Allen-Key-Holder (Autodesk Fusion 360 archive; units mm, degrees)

design "Allen-Key-Holder" references "Base"
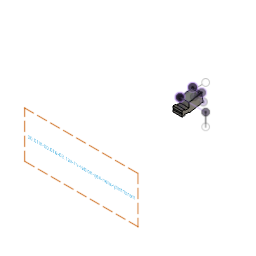
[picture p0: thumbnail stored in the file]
parameter "key_size" = 1.5
parameter "angle" = 10
parameter "head_length" = 10
parameter "padding" = 5
parameter "key_tolerance" = 1
parameter "calculated_width_height" = 14 (= "if(padding + padding + key_size < 14 mm; 14 mm; padding + padding + key_size)")
parameter "rounded_inset_depth" = 30
parameter "length_tolerance" = 5
component_insert "Component Insert" Text1-Height 5 AlongDistance 3.175 Linear Dimension-2 30 (= "rounded_inset_depth") Linear Dimension-3 30 (= "rounded_inset_depth") Side1Offset 0 TaperAngle 0 Linear Dimension-2 30 (= "rounded_inset_depth") Linear Dimension-3 30 (= "rounded_inset_depth") Side1Offset 0 TaperAngle 0 Radius 40
work_plane "WorkPlane5" AlongDistance 55.612
sketch "Sketch12" plane through (0, 55.6118, 0) normal (0, 1, 0) x axis (1, 0, 0)
  line L1 (40, -60) -> (0, -60)
  line L2 (40, -40) -> (40, -60)
  point P3 (40, -60)
  point P4 (40, -60)
  coincident P3 P4
  perpendicular L1 L2
sketch "Side" plane through (0, 0, 0) normal (1, 0, 0) x axis (0, 1, 0)
  line L1 (75.308, 63.473) -> (55.6118, 60)
  line L2 (95.6118, 60) -> (55.6118, 60)
  point P2 (55.6118, 60)
  point P3 (55.6118, 60)
  point P4 (75.308, 63.473)
  horizontal L2
  coincident P2 P3
  dimension "d66" distance P3 P4 = 20 (= "10 mm + head_length")
  dimension "d67" angle L1 L2 = 10 (= "angle")
work_plane "WorkPlane6" RotateAngle 90
sketch "Top" plane through (0, -8.5837, 48.6806) normal (0, 0.1736, -0.9848) x axis (0, 0.9848, 0.1736)
  line L1 (65.1859, 14) -> (65.1859, 0)
  line L2 (85.1859, 14) -> (65.1859, 14)
  line L3 (85.1859, 0) -> (65.1859, 0)
  line L4 (85.1859, 0) -> (85.1859, 14)
  point P3 (65.1859, 0)
  point P4 (65.1859, 0)
  point P2 (85.1859, 0)
  point P9 (85.1859, 0)
  point P5 (65.1859, 14)
  coincident P3 P4
  vertical L1
  perpendicular L1 L2
  equal L2 L3
  coincident P2 P9
  dimension "d69" distance P4 P5 = 14 (= "calculated_width_height")
extrude "Extrude18" new body sketch "Top" along a picked direction blind 14 (= "calculated_width_height")
extrude "Extrude15" new body of existing geometry blind 68
sketch "Front" plane through (0, 83.8917, 14.7924) normal (0, 0.9848, 0.1736) x axis (-1, 0, 0)
  line L1 (-14, 49.4316) -> (0, 49.4316)
  line L2 (-14, 35.4316) -> (-14, 49.4316)
  line L3 (0, 35.4316) -> (-14, 35.4316)
  line L4 (0, 49.4316) -> (0, 35.4316)
  line L5 (0, 35.4316) -> (-14, 49.4316)
  line L6 (-8.4434, 42.4316) -> (-7.7217, 43.6816)
  line L7 (-7.7217, 41.1816) -> (-8.4434, 42.4316)
  line L8 (-6.2783, 41.1816) -> (-7.7217, 41.1816)
  line L9 (-5.5566, 42.4316) -> (-6.2783, 41.1816)
  line L10 (-6.2783, 43.6816) -> (-5.5566, 42.4316)
  line L11 (-7.7217, 43.6816) -> (-6.2783, 43.6816)
  line L12 (0, 49.4316) -> (-14, 49.4316)
  point P3 (-14, 49.4316)
  point P6 (-14, 49.4316)
  point P5 (0, 35.4316)
  point P7 (0, 35.4316)
  point P14 (-7, 42.4316)
  coincident P3 P6
  coincident P5 P7
  midpoint L5 P14
  parallel L11 L12
  dimension "d91" distance P14 L11 = 1.25 (= "( key_size + key_tolerance ) / 2")
extrude "Extrude19" cut sketch "Front" profile of L6 L7 L8 L9 L10 L11 along a picked direction blind -10 (= "head_length * -1")
sketch "Sketch20" plane through (0, 0, 0) normal (-1, 0, 0) x axis (0, -1, 0)
  line L1 (-75.308, 63.473) -> (-55.6118, 60)
  line L2 (-77.7391, 49.6857) -> (-75.308, 63.473)
  line L3 (-58.0429, 46.2127) -> (-77.7391, 49.6857)
  line L4 (-55.6118, 60) -> (-58.0429, 46.2127)
  line L5 (-55.6118, 46.1062) -> (-55.6118, 60)
  line L6 (-58.0429, 46.2127) -> (-55.6118, 46.1062)
  point P6 (-55.6118, 60)
  point P8 (-55.6118, 60)
  point P7 (-58.0429, 46.2127)
  point P10 (-58.0429, 46.2127)
  coincident P6 P8
  vertical L5
  coincident P7 P10
extrude "Extrude20" add sketch "Sketch20" profile of L4 L5 L6 to an object
extrude "Extrude21" add of existing geometry to an object
extrude "Extrude22" cut of existing geometry to an object
fillet "Fillet3" radius 2
sketch "Sketch21" plane through (0, -6.1526, 34.8933) normal (0, 0.1736, -0.9848) x axis (-1, 0, 0)
  dimension "d102" = 2.5
sketch "File name" plane through (0, 0, 0) normal (0, 1, 0) x axis (1, 0, 0)
  dimension "d87" = 5
extrude "Extrude23" cut sketch "Sketch21" against normal blind 2

design "Base"
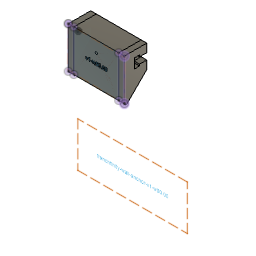
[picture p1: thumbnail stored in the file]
parameter "wall_anchor_height" = 60
parameter "wall_anchor_width" = 20
parameter "wall_anchor_angle" = 45
parameter "width_per_slot" = 40
parameter "slot_inner_width" = 8.5
parameter "slot_inner_height" = 4.5
parameter "slot_outer_width" = 5.6
parameter "slot_outer_height" = 6.5
parameter "slot_dept" = 15
parameter "print_tolerance" = 0.12
parameter "base_plate_thickness" = 16
parameter "base_plate_slot_height" = 50
parameter "wall_anchor_angle_rounded_border" = 1.5
parameter "base_plate_screw_hole_diameter" = 4
parameter "base_plate_screw_head_diameter" = 8
parameter "base_plate_screw_head_height" = 4
parameter "base_plate_screw_hole_side_distance" = 7
parameter "slot_screw_head_width" = 4.42 (= "4.3 mm + print_tolerance")
parameter "slot_screw_thread_width" = 2.12 (= "2 mm + print_tolerance")
parameter "slot_screw_head_height" = 2.12 (= "2 mm + print_tolerance")
parameter "width" = 50
parameter "filament_hole_width" = 1.7
sketch "Side" plane through (0, 0, 0) normal (1, 0, 0) x axis (0, 1, 0)
  line L1 (39.6118, 0) -> (19.6118, 0)
  line L2 (39.6118, 60) -> (39.6118, 0)
  line L3 (19.6118, 60) -> (39.6118, 60)
  line L4 (19.6118, 0) -> (19.6118, 60)
  line L5 (39.6118, 39.6118) -> (0, 0)
  line L6 (56.0196, 0) -> (0, 0)
  point P1 (0, 0)
  point P6 (0, 0)
  point P7 (39.6118, 39.6118)
  point P2 (19.6118, 0)
  point P3 (39.6118, 0)
  point P5 (19.6118, 60)
  horizontal L1
  vertical L2
  horizontal L3
  vertical L4
  horizontal L6
  coincident P1 P6
  coincident L2 P7
  dimension "d4" distance P2 P3 = 20 (= "wall_anchor_width")
  dimension "d5" distance P2 P5 = 60 (= "wall_anchor_height")
  dimension "d6" angle L5 L6 = 45 (= "wall_anchor_angle")
extrude "Extrude1" new body sketch "Side" profile of L1 L2 L3 L4 L5 along normal blind 40 (= "width_per_slot")
sketch "Slot LeftToRight" plane through (0, 0, 0) normal (-1, 0, 0) x axis (0, -1, 0)
  line L1 (-19.6118, 60) -> (-19.6118, 19.6118)
  line L2 (-39.6118, 60) -> (-19.6118, 60)
  line L3 (-39.6118, 39.6118) -> (-39.6118, 60)
  line L4 (-19.6118, 19.6118) -> (-39.6118, 39.6118)
  line L5 (-39.6118, 52.6059) -> (-39.6118, 49.8059)
  line L6 (-39.6118, 47.0059) -> (-39.6118, 49.8059)
  line L7 (-33.1118, 52.6059) -> (-39.6118, 52.6059)
  line L8 (-28.6118, 49.8059) -> (-39.6118, 49.8059)
  line L9 (-28.6118, 54.0559) -> (-28.6118, 49.8059)
  line L10 (-33.1118, 54.0559) -> (-28.6118, 54.0559)
  line L11 (-33.1118, 52.6059) -> (-33.1118, 54.0559)
  line L12 (-28.6118, 45.5559) -> (-28.6118, 49.8059)
  line L13 (-33.1118, 45.5559) -> (-28.6118, 45.5559)
  line L14 (-33.1118, 47.0059) -> (-33.1118, 45.5559)
  line L15 (-33.1118, 47.0059) -> (-39.6118, 47.0059)
  point P6 (-39.6118, 49.8059)
  point P7 (-39.6118, 52.6059)
  point P17 (-39.6118, 47.0059)
  point P9 (-33.1118, 52.6059)
  point P16 (-33.1118, 47.0059)
  point P10 (-28.6118, 49.8059)
  point P13 (-28.6118, 49.8059)
  point P11 (-28.6118, 54.0559)
  point P14 (-28.6118, 45.5559)
  point P12 (-33.1118, 54.0559)
  point P15 (-33.1118, 45.5559)
  midpoint L3 P6
  parallel L3 L5
  parallel L3 L6
  perpendicular L3 L7
  perpendicular L6 L8
  perpendicular L8 L9
  perpendicular L9 L10
  symmetric P7 L8 P17
  symmetric P9 L8 P16
  symmetric P10 L8 P13
  symmetric L8 P11 P14
  symmetric L8 P12 P15
  dimension "d80" distance P6 P7 = 2.8 (= "slot_outer_width / 2")
  dimension "d82" distance P7 P9 = 6.5 (= "slot_outer_height")
  dimension "d84" distance P6 P10 = 11 (= "slot_outer_height + slot_inner_height")
  dimension "d85" distance P10 P11 = 4.25 (= "slot_inner_width / 2")
  dimension "d86" distance P11 P12 = 4.5 (= "slot_inner_height")
extrude "Extrude3" cut sketch "Slot LeftToRight" profile of L3 L5 L6 L7 L9 L10 L11 L12 L13 L14 L15 against normal blind 40 (magnitude of "width_per_slot * -1")
sketch "Plate" plane through (0, 39.6118, 0) normal (0, 1, 0) x axis (-1, 0, 0)
  line L1 (0, 39.6118) -> (-40, 39.6118)
  line L2 (-40, 60) -> (0, 60)
  line L3 (0, 10) -> (0, 60)
  line L4 (-40, 10) -> (-40, 60)
  line L5 (-40, 10) -> (0, 10)
  line L6 (-40, 47.0059) -> (0, 47.0059)
  line L7 (-40, 52.6059) -> (-40, 60)
  line L8 (0, 60) -> (0, 52.6059)
  line L9 (0, 52.6059) -> (-40, 52.6059)
  line L10 (-40, 60) -> (0, 60)
  line L11 (-40, 39.6118) -> (-40, 47.0059)
  line L12 (0, 47.0059) -> (0, 39.6118)
  point P2 (0, 60)
  point P3 (-40, 60)
  point P4 (0, 10)
  point P5 (-40, 10)
  perpendicular L1 L3
  perpendicular L1 L4
  dimension "d36" distance P2 P3 = 40 (= "width_per_slot")
  dimension "d37" distance P2 P4 = 50 (= "base_plate_slot_height")
  dimension "d39" distance P3 P5 = 50 (= "base_plate_slot_height")
extrude "Extrude6" new body sketch "Plate" profile of L1 L2 L3 L4 L5 L6 L7 L8 L9 L10 along normal blind 16 (= "base_plate_thickness") bodies "Base plate with slot"
sketch "Slot" plane through (0, 0, 0) normal (-1, 0, 0) x axis (0, -1, 0)
  line L1 (-19.6118, 60) -> (-19.6118, 19.6118)
  line L2 (-39.6118, 60) -> (-19.6118, 60)
  line L3 (-39.6118, 52.6059) -> (-39.6118, 60)
  line L4 (-33.1118, 52.6059) -> (-39.6118, 52.6059)
  line L5 (-33.1118, 54.0559) -> (-33.1118, 52.6059)
  line L6 (-28.6118, 54.0559) -> (-33.1118, 54.0559)
  line L7 (-28.6118, 45.5559) -> (-28.6118, 54.0559)
  line L8 (-33.1118, 45.5559) -> (-28.6118, 45.5559)
  line L9 (-33.1118, 47.0059) -> (-33.1118, 45.5559)
  line L10 (-39.6118, 47.0059) -> (-33.1118, 47.0059)
  line L11 (-39.6118, 39.6118) -> (-39.6118, 47.0059)
  line L12 (-19.6118, 19.6118) -> (-39.6118, 39.6118)
  line L13 (-33.1118, 52.6059) -> (-39.6118, 52.6059)
  line L14 (-33.1118, 54.0559) -> (-33.1118, 52.6059)
  line L15 (-28.6118, 54.0559) -> (-33.1118, 54.0559)
  line L16 (-28.6118, 45.5559) -> (-28.6118, 54.0559)
  line L17 (-33.1118, 45.5559) -> (-28.6118, 45.5559)
  line L18 (-33.1118, 47.0059) -> (-33.1118, 45.5559)
  line L19 (-39.6118, 47.0059) -> (-33.1118, 47.0059)
  line L20 (-39.6118, 10) -> (-39.6118, 60)
  line L21 (-32.9918, 52.4859) -> (-39.6118, 52.4859)
  line L22 (-32.9918, 53.9359) -> (-32.9918, 52.4859)
  line L23 (-28.7318, 53.9359) -> (-32.9918, 53.9359)
  line L24 (-28.7318, 45.6759) -> (-28.7318, 53.9359)
  line L25 (-32.9918, 45.6759) -> (-28.7318, 45.6759)
  line L26 (-32.9918, 47.1259) -> (-32.9918, 45.6759)
  line L27 (-39.6118, 47.1259) -> (-32.9918, 47.1259)
  line L28 (-33.1118, 52.6059) -> (-39.6118, 52.6059)
  line L29 (-33.1118, 52.6059) -> (-33.1118, 54.0559)
  line L30 (-28.6118, 54.0559) -> (-33.1118, 54.0559)
  line L31 (-28.6118, 45.5559) -> (-28.6118, 54.0559)
  line L32 (-33.1118, 45.5559) -> (-28.6118, 45.5559)
  line L33 (-33.1118, 47.0059) -> (-33.1118, 45.5559)
  line L34 (-39.6118, 47.0059) -> (-33.1118, 47.0059)
  line L35 (-39.6118, 47.0059) -> (-39.6118, 52.6059)
  line L36 (-49.1118, 52.6059) -> (-55.6118, 52.6059)
  line L37 (-49.1118, 52.6059) -> (-49.1118, 54.0559)
  line L38 (-44.6118, 54.0559) -> (-49.1118, 54.0559)
  line L39 (-44.6118, 45.5559) -> (-44.6118, 54.0559)
  line L40 (-49.1118, 45.5559) -> (-44.6118, 45.5559)
  line L41 (-49.1118, 47.0059) -> (-49.1118, 45.5559)
  line L42 (-55.6118, 47.0059) -> (-49.1118, 47.0059)
  line L43 (-55.6118, 47.0059) -> (-55.6118, 52.6059)
  point P15 (-39.6118, 52.6059)
  point P33 (-39.6118, 52.6059)
  point P16 (-33.1118, 52.6059)
  point P34 (-33.1118, 52.6059)
  point P17 (-33.1118, 54.0559)
  point P35 (-33.1118, 54.0559)
  point P36 (-33.1118, 52.6059)
  point P18 (-28.6118, 54.0559)
  point P37 (-28.6118, 54.0559)
  point P19 (-28.6118, 45.5559)
  point P38 (-28.6118, 45.5559)
  point P10 (-28.6118, 45.5559)
  point P39 (-28.6118, 45.5559)
  point P11 (-33.1118, 45.5559)
  point P40 (-33.1118, 45.5559)
  point P41 (-33.1118, 45.5559)
  point P12 (-33.1118, 47.0059)
  point P42 (-33.1118, 47.0059)
  point P21 (-33.1118, 47.0059)
  point P43 (-33.1118, 47.0059)
  point P22 (-39.6118, 47.0059)
  point P44 (-39.6118, 47.0059)
  point P45 (-39.6118, 52.6059)
  point P46 (-39.6118, 47.0059)
  coincident P15 P33
  coincident P16 P34
  coincident P17 P35
  coincident P16 P36
  coincident P18 P37
  coincident P19 P38
  coincident P10 P39
  coincident P11 P40
  coincident P11 P41
  coincident P12 P42
  coincident P21 P43
  coincident P22 P44
  coincident P15 P45
  coincident P22 P46
  dimension "d91" = 0.12 (= "print_tolerance")
  dimension "d96" R-Pattern1-uDistance = -16 (= "base_plate_thickness * -1")
  dimension "d97" R-Pattern1-vDistance = 0
extrude "Extrude7" add sketch "Slot" profile of L20 L24 L23 L27 L22 L25 L26 L21 against normal blind 40 (magnitude of "width_per_slot * -1")
extrude "Extrude8" cut sketch "Slot" profile of L36 L37 L38 L39 L40 L41 L42 L43 no distance stored
sketch "Sketch3" plane through (0, 0, 0) normal (-1, 0, 0) x axis (0, -1, 0)
  line L1 (-32.9918, 47.1259) -> (-39.6118, 47.1259)
  line L2 (-32.9918, 45.6759) -> (-32.9918, 47.1259)
  line L3 (-28.7318, 45.6759) -> (-32.9918, 45.6759)
  line L4 (-28.7318, 53.9359) -> (-28.7318, 45.6759)
  line L5 (-32.9918, 53.9359) -> (-28.7318, 53.9359)
  line L6 (-32.9918, 52.4859) -> (-32.9918, 53.9359)
  line L7 (-39.6118, 52.4859) -> (-32.9918, 52.4859)
  line L8 (-44.6118, 45.5559) -> (-44.6118, 54.0559)
  line L9 (-32.9918, 52.4859) -> (-39.6118, 52.4859)
  line L10 (-32.9918, 53.9359) -> (-32.9918, 52.4859)
  line L11 (-28.7318, 53.9359) -> (-32.9918, 53.9359)
  line L12 (-28.7318, 45.6759) -> (-28.7318, 53.9359)
  line L13 (-32.9918, 45.6759) -> (-28.7318, 45.6759)
  line L14 (-32.9918, 47.1259) -> (-32.9918, 45.6759)
  line L15 (-39.6118, 47.1259) -> (-32.9918, 47.1259)
  line L16 (-39.6118, 47.1259) -> (-39.6118, 52.4859)
  line L17 (-55.6118, 52.4859) -> (-48.9918, 52.4859)
  line L18 (-48.9918, 52.4859) -> (-48.9918, 53.9359)
  line L19 (-48.9918, 53.9359) -> (-44.7318, 53.9359)
  line L20 (-44.7318, 45.6759) -> (-44.7318, 53.9359)
  line L21 (-48.9918, 45.6759) -> (-44.7318, 45.6759)
  line L22 (-48.9918, 47.1259) -> (-48.9918, 45.6759)
  line L23 (-55.6118, 47.1259) -> (-48.9918, 47.1259)
  line L24 (-55.6118, 47.1259) -> (-55.6118, 52.4859)
  line L25 (-55.6118, 47.0059) -> (-49.1118, 47.0059)
  line L26 (-55.6118, 10) -> (-55.6118, 47.0059)
  line L27 (-39.6118, 10) -> (-55.6118, 10)
  line L28 (-39.6118, 47.1259) -> (-39.6118, 10)
  line L29 (-39.6118, 60) -> (-39.6118, 52.4859)
  line L30 (-55.6118, 60) -> (-39.6118, 60)
  line L31 (-55.6118, 52.6059) -> (-55.6118, 60)
  line L32 (-49.1118, 52.6059) -> (-55.6118, 52.6059)
  line L33 (-49.1118, 54.0559) -> (-49.1118, 52.6059)
  line L34 (-44.6118, 54.0559) -> (-49.1118, 54.0559)
  line L35 (-49.1118, 45.5559) -> (-44.6118, 45.5559)
  line L36 (-49.1118, 47.0059) -> (-49.1118, 45.5559)
  point P9 (-39.6118, 52.4859)
  point P20 (-39.6118, 52.4859)
  point P19 (-39.6118, 47.1259)
  point P21 (-39.6118, 47.1259)
  coincident P9 P20
  coincident P19 P21
  dimension "d105" R-Pattern1-vDistance = 0
extrude "Extrude3" new body sketch "Sketch3" profile of L17 L18 L19 L20 L21 L22 L23 L24 against normal blind 40 (magnitude of "width_per_slot * -1")
sketch "Screw hole" plane through (0, 28.6118, 0) normal (0, 1, 0) x axis (-1, 0, 0)
  line L1 (0, 54.0559) -> (0, 45.5559)
  line L2 (-40, 54.0559) -> (0, 54.0559)
  line L3 (-40, 45.5559) -> (-40, 54.0559)
  line L4 (0, 45.5559) -> (-40, 45.5559)
  line L5 (0, 45.5559) -> (-40, 54.0559)
  line L6 (-40, 45.5559) -> (0, 54.0559)
  circle C1 centre (-20, 49.8059) radius 2.21
  circle C2 centre (-20, 49.8059) radius 1.06
  point P4 (-40, 54.0559)
  point P6 (-40, 54.0559)
  point P2 (0, 45.5559)
  point P7 (0, 45.5559)
  point P3 (0, 54.0559)
  point P8 (0, 54.0559)
  point P5 (-40, 45.5559)
  point P9 (-40, 45.5559)
  point P10 (-20, 49.8059)
  coincident P4 P6
  coincident P2 P7
  coincident P3 P8
  coincident P5 P9
  midpoint L5 P10
  concentric C1 C2
  dimension "d119" diameter C1 = 4.42 (= "slot_screw_head_width")
  dimension "d120" diameter C2 = 2.12 (= "slot_screw_thread_width")
extrude "Extrude4" cut sketch "Screw hole" profile of C2 against normal blind 2000
extrude "Extrude5" cut sketch "Screw hole" profile of C1 C2 no distance stored
fillet "Fillet1" radius 1.5 (= "wall_anchor_angle_rounded_border")
work_plane "WorkPlane1" sketch "Slot LeftToRight" AlongDistance -20 (= "-width_per_slot / 2")
sketch "Screw head" plane through (20, 0, 0) normal (-1, 0, 0) x axis (0, -1, 0)
  line L1 (-28.6118, 52.0159) -> (-28.6118, 47.5959)
  line L2 (-26.4918, 52.0159) -> (-26.4918, 47.5959)
  line L3 (-26.4918, 48.7459) -> (-26.4918, 50.8659)
  line L4 (-26.4918, 50.8659) -> (-28.6118, 52.0159)
  line L5 (-26.4918, 52.0159) -> (-28.6118, 52.0159)
  point P3 (-28.6118, 52.0159)
  point P8 (-28.6118, 52.0159)
  point P6 (-26.4918, 50.8659)
  point P9 (-26.4918, 50.8659)
  point P10 (-28.6118, 52.0159)
  point P5 (-26.4918, 52.0159)
  point P11 (-26.4918, 52.0159)
  coincident P3 P8
  coincident P6 P9
  coincident P3 P10
  coincident P5 P11
revolve "Revolve1" sketch "Screw head" AlongAngle 360
sketch "Plate" plane through (0, 39.6118, 0) normal (0, 1, 0) x axis (-1, 0, 0)
  line L1 (0, 39.6118) -> (-40, 39.6118)
  line L2 (-40, 60) -> (0, 60)
  line L3 (0, 10) -> (0, 60)
  line L4 (-40, 10) -> (-40, 60)
  line L5 (-40, 10) -> (0, 10)
  line L6 (-40, 47.0059) -> (0, 47.0059)
  line L7 (-40, 39.6118) -> (-40, 47.0059)
  line L8 (0, 47.0059) -> (0, 39.6118)
  line L9 (0, 52.6059) -> (-40, 52.6059)
  line L10 (-40, 60) -> (0, 60)
  line L11 (0, 60) -> (0, 52.6059)
  line L12 (-40, 52.6059) -> (-40, 60)
  point P2 (0, 60)
  point P3 (-40, 60)
  point P4 (0, 10)
  point P5 (-40, 10)
  perpendicular L1 L3
  perpendicular L1 L4
  dimension "d36_1" distance P2 P3 = 40 (= "width_per_slot")
  dimension "d37_1" distance P2 P4 = 50 (= "base_plate_slot_height")
  dimension "d39_1" distance P3 P5 = 50 (= "base_plate_slot_height")
extrude "Extrude6" new body sketch "Plate" profile of L1 L2 L3 L4 L5 L6 L7 L8 L9 L10 along normal blind 16 (= "base_plate_thickness") named "d89_1" bodies "Base plate with slot"
sketch "Slot" plane through (0, 0, 0) normal (-1, 0, 0) x axis (0, -1, 0)
  line L1 (-19.6118, 60) -> (-19.6118, 23.2332)
  line L2 (-39.6118, 60) -> (-19.6118, 60)
  line L3 (-39.6118, 52.6059) -> (-39.6118, 60)
  line L4 (-33.1118, 52.6059) -> (-39.6118, 52.6059)
  line L5 (-33.1118, 54.0559) -> (-33.1118, 52.6059)
  line L6 (-28.6118, 54.0559) -> (-33.1118, 54.0559)
  line L7 (-28.6118, 45.5559) -> (-28.6118, 54.0559)
  line L8 (-33.1118, 45.5559) -> (-28.6118, 45.5559)
  line L9 (-33.1118, 47.0059) -> (-33.1118, 45.5559)
  line L10 (-39.6118, 47.0059) -> (-33.1118, 47.0059)
  line L11 (-39.6118, 39.6118) -> (-39.6118, 47.0059)
  line L12 (-22.1725, 22.1725) -> (-39.6118, 39.6118)
  line L13 (-33.1118, 52.6059) -> (-39.6118, 52.6059)
  line L14 (-33.1118, 54.0559) -> (-33.1118, 52.6059)
  line L15 (-28.6118, 54.0559) -> (-33.1118, 54.0559)
  line L16 (-28.6118, 45.5559) -> (-28.6118, 54.0559)
  line L17 (-33.1118, 45.5559) -> (-28.6118, 45.5559)
  line L18 (-33.1118, 47.0059) -> (-33.1118, 45.5559)
  line L19 (-39.6118, 47.0059) -> (-33.1118, 47.0059)
  line L20 (-39.6118, 10) -> (-39.6118, 60)
  line L21 (-32.9918, 52.4859) -> (-39.6118, 52.4859)
  line L22 (-32.9918, 53.9359) -> (-32.9918, 52.4859)
  line L23 (-28.7318, 53.9359) -> (-32.9918, 53.9359)
  line L24 (-28.7318, 45.6759) -> (-28.7318, 53.9359)
  line L25 (-32.9918, 45.6759) -> (-28.7318, 45.6759)
  line L26 (-32.9918, 47.1259) -> (-32.9918, 45.6759)
  line L27 (-39.6118, 47.1259) -> (-32.9918, 47.1259)
  line L28 (-33.1118, 52.6059) -> (-39.6118, 52.6059)
  line L29 (-33.1118, 52.6059) -> (-33.1118, 54.0559)
  line L30 (-28.6118, 54.0559) -> (-33.1118, 54.0559)
  line L31 (-28.6118, 45.5559) -> (-28.6118, 54.0559)
  line L32 (-33.1118, 45.5559) -> (-28.6118, 45.5559)
  line L33 (-33.1118, 47.0059) -> (-33.1118, 45.5559)
  line L34 (-39.6118, 47.0059) -> (-33.1118, 47.0059)
  line L35 (-39.6118, 47.0059) -> (-39.6118, 52.6059)
  line L36 (-49.1118, 52.6059) -> (-55.6118, 52.6059)
  line L37 (-49.1118, 52.6059) -> (-49.1118, 54.0559)
  line L38 (-44.6118, 54.0559) -> (-49.1118, 54.0559)
  line L39 (-44.6118, 45.5559) -> (-44.6118, 54.0559)
  line L40 (-49.1118, 45.5559) -> (-44.6118, 45.5559)
  line L41 (-49.1118, 47.0059) -> (-49.1118, 45.5559)
  line L42 (-55.6118, 47.0059) -> (-49.1118, 47.0059)
  line L43 (-55.6118, 47.0059) -> (-55.6118, 52.6059)
  arc A1 centre (-21.1118, 23.2332) radius 1.5 clockwise from (-19.6118, 23.2332) to (-22.1725, 22.1725)
  point P15 (-39.6118, 52.6059)
  point P33 (-39.6118, 52.6059)
  point P16 (-33.1118, 52.6059)
  point P34 (-33.1118, 52.6059)
  point P17 (-33.1118, 54.0559)
  point P35 (-33.1118, 54.0559)
  point P36 (-33.1118, 52.6059)
  point P18 (-28.6118, 54.0559)
  point P37 (-28.6118, 54.0559)
  point P19 (-28.6118, 45.5559)
  point P38 (-28.6118, 45.5559)
  point P10 (-28.6118, 45.5559)
  point P39 (-28.6118, 45.5559)
  point P11 (-33.1118, 45.5559)
  point P40 (-33.1118, 45.5559)
  point P41 (-33.1118, 45.5559)
  point P12 (-33.1118, 47.0059)
  point P42 (-33.1118, 47.0059)
  point P21 (-33.1118, 47.0059)
  point P43 (-33.1118, 47.0059)
  point P22 (-39.6118, 47.0059)
  point P44 (-39.6118, 47.0059)
  point P45 (-39.6118, 52.6059)
  point P46 (-39.6118, 47.0059)
  coincident P15 P33
  coincident P16 P34
  coincident P17 P35
  coincident P16 P36
  coincident P18 P37
  coincident P19 P38
  coincident P10 P39
  coincident P11 P40
  coincident P11 P41
  coincident P12 P42
  coincident P21 P43
  coincident P22 P44
  coincident P15 P45
  coincident P22 P46
  dimension "d91_1" = 0.12 (= "print_tolerance")
  dimension "d96_1" R-Pattern1-uDistance = -16 (= "base_plate_thickness * -1")
  dimension "d97_1" R-Pattern1-vDistance = 0
extrude "Extrude8" cut sketch "Slot" profile of L36 L37 L38 L39 L40 L41 L42 L43 no distance stored
sketch "Screw" plane through (0, 55.6118, 0) normal (0, 1, 0) x axis (-1, 0, 0)
  line L1 (-40, 47.0059) -> (0, 47.0059)
  line L2 (-40, 10) -> (-40, 47.0059)
  line L3 (0, 10) -> (-40, 10)
  line L4 (0, 47.0059) -> (0, 10)
  line L5 (-33, 17) -> (-33, 40.0059)
  line L6 (-7, 17) -> (-33, 17)
  line L7 (-7, 40.0059) -> (-7, 17)
  line L8 (-33, 40.0059) -> (-7, 40.0059)
  circle C1 centre (-33, 17) radius 4
  circle C2 centre (-33, 17) radius 2
  point P7 (-33, 17)
  point P10 (-33, 17)
  coincident P7 P10
  concentric C1 C2
  dimension "d127" = -7 (= "base_plate_screw_hole_side_distance * -1")
  dimension "d128" diameter C1 = 8
  dimension "d129" diameter C2 = 4
rectangular_pattern "R-Pattern2" countU 1 (= "floor(( width / mm ) / ( width_per_slot / cm * 10 ))") uSpaceDistance 40 (= "width_per_slot") vSpaceDistance 0
work_plane "WorkPlane2"
extrude "Extrude12" new body of existing geometry no distance stored
mirror "Mirror3" mirrorStitchTolerance 0.1
sketch "filename" plane through (0, 19.6118, 0) normal (0, -1, 0) x axis (1, 0, 0)
  dimension "d216" = 3
sketch "Sketch14" plane through (0, 19.6118, 0) normal (0, -1, 0) x axis (1, 0, 0)
  line L1 (45, 60) -> (45, 23.2332)
  line L2 (40, 23.2332) -> (40, 60)
  line L3 (45, 23.2332) -> (40, 23.2332)
  line L4 (45, 60) -> (45, 23.2332)
  line L5 (40, 60) -> (45, 60)
  line L6 (0, 60) -> (0, 23.2332)
  line L7 (-5, 60) -> (0, 60)
  line L8 (-5, 23.2332) -> (-5, 60)
  line L9 (0, 23.2332) -> (-5, 23.2332)
  curve K1
  curve K2
  curve K3
  curve K4
  point P4 (45, 23.2332)
  point P2 (-5, 60)
  coincident P4
  coincident P2
  dimension "d229" Text1-Height = 3
extrude "Extrude19" cut sketch "Sketch14" against normal blind 2
extrude "Extrude14" cut of existing geometry blind 5 (= "( width_per_slot - width ) / -2")
extrude "Extrude15" cut of existing geometry blind 5 (= "( width_per_slot - width ) / -2")
extrude "Extrude9" cut of existing geometry blind -39 (= "-width_per_slot + 1 mm")
extrude "Extrude10" add of existing geometry blind 49 (= "width - 1 mm")
sketch "Sketch7" plane through (0, 39.6118, 0) normal (0, -1, 0) x axis (1, 0, 0)
  dimension "d236" = 3
extrude "Extrude11" cut sketch "Sketch7" against normal blind 2
sketch "File name" plane through (0, 39.6118, 0) normal (0, -1, 0) x axis (1, 0, 0)
  line L1 (19.0624, 30.0752) -> (18.825, 30.0752)
  line L2 (19.0624, 27.063) -> (19.0624, 30.0752)
  line L3 (18.6941, 27.063) -> (19.0624, 27.063)
  line L4 (18.6941, 29.4102) -> (18.6941, 27.063)
  curve K1 (18.3441, 29.1564) -> (18.6941, 29.4102)
  curve K2 (17.9574, 28.9661) -> (18.3441, 29.1564)
  line L5 (17.9574, 29.3222) -> (17.9574, 28.9661)
  curve K3 (18.4976, 29.6741) -> (17.9574, 29.3222)
  curve K4 (18.825, 30.0752) -> (18.4976, 29.6741)
  line L6 (22.2896, 27.063) -> (22.7295, 28.7349)
  line L7 (21.9048, 27.063) -> (22.2896, 27.063)
  line L8 (21.2398, 29.2362) -> (21.9048, 27.063)
  line L9 (21.6204, 29.2362) -> (21.2398, 29.2362)
  line L10 (21.9662, 27.9818) -> (21.6204, 29.2362)
  line L11 (22.0952, 27.5152) -> (21.9662, 27.9818)
  curve K5 (22.2077, 27.9634) -> (22.0952, 27.5152)
  line L12 (22.5535, 29.2362) -> (22.2077, 27.9634)
  line L13 (22.9321, 29.2362) -> (22.5535, 29.2362)
  line L14 (23.2575, 27.9756) -> (22.9321, 29.2362)
  line L15 (23.366, 27.5602) -> (23.2575, 27.9756)
  line L16 (23.4908, 27.9797) -> (23.366, 27.5602)
  line L17 (23.8632, 29.2362) -> (23.4908, 27.9797)
  line L18 (24.2214, 29.2362) -> (23.8632, 29.2362)
  line L19 (23.542, 27.063) -> (24.2214, 29.2362)
  line L20 (23.1593, 27.063) -> (23.542, 27.063)
  line L21 (22.8134, 28.3645) -> (23.1593, 27.063)
  line L22 (22.7295, 28.7349) -> (22.8134, 28.3645)
  line L23 (21.0965, 27.9634) -> (21.0965, 28.3338)
  line L24 (19.9649, 27.9634) -> (21.0965, 27.9634)
  line L25 (19.9649, 28.3338) -> (19.9649, 27.9634)
  line L26 (21.0965, 28.3338) -> (19.9649, 28.3338)
  line L27 (16.6293, 27.063) -> (17.4519, 29.2362)
  line L28 (16.2855, 27.063) -> (16.6293, 27.063)
  line L29 (15.4587, 29.2362) -> (16.2855, 27.063)
  line L30 (15.8475, 29.2362) -> (15.4587, 29.2362)
  line L31 (16.3141, 27.9347) -> (15.8475, 29.2362)
  curve K6 (16.4533, 27.4968) -> (16.3141, 27.9347)
  curve K7 (16.5904, 27.9102) -> (16.4533, 27.4968)
  line L32 (17.0733, 29.2362) -> (16.5904, 27.9102)
  line L33 (17.4519, 29.2362) -> (17.0733, 29.2362)
  line L34 (0, 47.1259) -> (50, 47.1259)
  line L35 (0, 10) -> (0, 47.1259)
  line L36 (50, 10) -> (0, 10)
  line L37 (50, 47.1259) -> (50, 10)
  curve K8
  curve K9
  curve K10
  curve K11
  curve K12 (25.484, 29.052) -> (24.9171, 28.8638)
  curve K13 (25.3919, 27.3147) -> (25.0133, 27.4559)
  curve K14 (25.8421, 27.5152) -> (25.3919, 27.3147)
  curve K15 (25.8482, 28.5445) -> (26.0263, 28.0473)
  curve K16 (25.3857, 28.7267) -> (25.8482, 28.5445)
  curve K17 (25.0133, 27.4559) -> (24.8148, 27.8815)
  curve K18 (26.0263, 28.0473) -> (25.8421, 27.5152)
  curve K19 (25.0645, 28.6448) -> (25.3857, 28.7267)
  curve K20 (24.8394, 28.4361) -> (25.0645, 28.6448)
  curve K21 (26.4171, 28.08) -> (26.147, 28.7799)
  curve K22 (26.1797, 27.3761) -> (26.4171, 28.08)
  line L38 (24.8148, 27.8815) -> (24.428, 27.8488)
  curve K23 (26.147, 28.7799) -> (25.484, 29.052)
  curve K24 (24.7227, 27.241) -> (25.3919, 27.0118)
  curve K25 (24.428, 27.8488) -> (24.7227, 27.241)
  line L39 (24.4935, 28.4811) -> (24.8394, 28.4361)
  line L40 (24.7841, 30.022) -> (24.4935, 28.4811)
  line L41 (26.2759, 30.022) -> (24.7841, 30.022)
  line L42 (26.2759, 29.6701) -> (26.2759, 30.022)
  line L43 (25.0788, 29.6701) -> (26.2759, 29.6701)
  line L44 (24.9171, 28.8638) -> (25.0788, 29.6701)
  curve K26 (25.3919, 27.0118) -> (26.1797, 27.3761)
  curve K27 (33.9867, 29.977) -> (33.5631, 30.0752)
  curve K28 (34.2875, 29.6967) -> (33.9867, 29.977)
  curve K29 (32.6934, 29.3979) -> (32.5849, 28.5425)
  curve K30 (33.0188, 29.8992) -> (32.6934, 29.3979)
  curve K31 (33.5631, 30.0752) -> (33.0188, 29.8992)
  curve K32 (34.4737, 29.2505) -> (34.2875, 29.6967)
  curve K33 (31.9567, 29.6967) -> (31.6559, 29.977)
  curve K34 (32.1429, 29.2505) -> (31.9567, 29.6967)
  curve K35 (30.3626, 29.3979) -> (30.2541, 28.5425)
  curve K36 (30.6879, 29.8992) -> (30.3626, 29.3979)
  curve K37 (31.2323, 30.0752) -> (30.6879, 29.8992)
  curve K38 (31.6559, 29.977) -> (31.2323, 30.0752)
  curve K39 (32.8817, 27.3228) -> (33.5631, 27.0118)
  curve K40 (32.5849, 28.5425) -> (32.8817, 27.3228)
  curve K41 (34.5413, 28.5425) -> (34.4737, 29.2505)
  curve K42 (34.4328, 27.6892) -> (34.5413, 28.5425)
  curve K43 (34.1074, 27.1878) -> (34.4328, 27.6892)
  curve K44 (33.5631, 27.0118) -> (34.1074, 27.1878)
  curve K45 (27.0556, 27.3228) -> (27.737, 27.0118)
  curve K46 (26.7589, 28.5425) -> (27.0556, 27.3228)
  curve K47 (26.8673, 29.3979) -> (26.7589, 28.5425)
  curve K48 (27.1927, 29.8992) -> (26.8673, 29.3979)
  curve K49 (27.737, 30.0752) -> (27.1927, 29.8992)
  curve K50 (28.1606, 29.977) -> (27.737, 30.0752)
  curve K51 (28.4615, 29.6967) -> (28.1606, 29.977)
  curve K52 (28.6477, 29.2505) -> (28.4615, 29.6967)
  curve K53 (28.7152, 28.5425) -> (28.6477, 29.2505)
  curve K54 (28.6068, 27.6892) -> (28.7152, 28.5425)
  curve K55 (28.2814, 27.1878) -> (28.6068, 27.6892)
  curve K56 (27.737, 27.0118) -> (28.2814, 27.1878)
  curve K57 (30.5508, 27.3228) -> (31.2323, 27.0118)
  curve K58 (30.2541, 28.5425) -> (30.5508, 27.3228)
  curve K59 (32.2104, 28.5425) -> (32.1429, 29.2505)
  curve K60 (32.102, 27.6892) -> (32.2104, 28.5425)
  curve K61 (31.7766, 27.1878) -> (32.102, 27.6892)
  curve K62 (31.2323, 27.0118) -> (31.7766, 27.1878)
  line L45 (29.7159, 27.063) -> (29.7159, 27.4825)
  line L46 (29.2964, 27.063) -> (29.7159, 27.063)
  line L47 (29.2964, 27.4825) -> (29.2964, 27.063)
  line L48 (29.7159, 27.4825) -> (29.2964, 27.4825)
  dimension "d239" Text1-Height = 3
sketch "Sketch4" plane through (40, 0, 0) normal (1, 0, 0) x axis (0, 1, 0)
  line L1 (44.7318, 53.9359) -> (48.9918, 53.9359)
  line L2 (44.7318, 45.6759) -> (44.7318, 53.9359)
  line L3 (48.9918, 45.6759) -> (44.7318, 45.6759)
  line L4 (48.9918, 47.1259) -> (48.9918, 45.6759)
  line L5 (55.6118, 47.1259) -> (48.9918, 47.1259)
  line L6 (55.6118, 52.4859) -> (55.6118, 47.1259)
  line L7 (48.9918, 52.4859) -> (55.6118, 52.4859)
  line L8 (48.9918, 53.9359) -> (48.9918, 52.4859)
  circle C1 centre (44.7318, 49.8059) radius 0.85
  point P10 (44.7318, 49.8059)
  midpoint L2 P10
  dimension "d241" diameter C1 = 1.7 (= "filament_hole_width")
extrude "Extrude4" cut sketch "Sketch4" profile of L2 C1 no distance stored
sketch "Sketch15" plane through (-5, 0, 0) normal (-1, 0, 0) x axis (0, -1, 0)
  line L1 (-19.6118, 60) -> (-19.6118, 23.2332)
  line L2 (-39.6118, 60) -> (-19.6118, 60)
  line L3 (-39.6118, 52.6059) -> (-39.6118, 60)
  line L4 (-33.1118, 52.6059) -> (-39.6118, 52.6059)
  line L5 (-33.1118, 54.0559) -> (-33.1118, 52.6059)
  line L6 (-28.6118, 54.0559) -> (-33.1118, 54.0559)
  line L7 (-28.6118, 45.5559) -> (-28.6118, 54.0559)
  line L8 (-33.1118, 45.5559) -> (-28.6118, 45.5559)
  line L9 (-33.1118, 47.0059) -> (-33.1118, 45.5559)
  line L10 (-39.6118, 47.0059) -> (-33.1118, 47.0059)
  line L11 (-39.6118, 39.6118) -> (-39.6118, 47.0059)
  line L12 (-22.1725, 22.1725) -> (-39.6118, 39.6118)
  arc A1 centre (-21.1118, 23.2332) radius 1.5 clockwise from (-19.6118, 23.2332) to (-22.1725, 22.1725)
  circle C1 centre (-28.6118, 49.8059) radius 0.85
  point P16 (-28.6118, 49.8059)
  midpoint L7 P16
  dimension "d244" diameter C1 = 1.7 (= "filament_hole_width")
sketch "Sketch9" plane through (50, 0, 0) normal (1, 0, 0) x axis (0, 1, 0)
  line L1 (49.1118, 47.0059) -> (55.6118, 47.0059)
  line L2 (49.1118, 45.5559) -> (49.1118, 47.0059)
  line L3 (44.6118, 45.5559) -> (49.1118, 45.5559)
  line L4 (44.6118, 54.0559) -> (44.6118, 45.5559)
  line L5 (49.1118, 54.0559) -> (44.6118, 54.0559)
  line L6 (49.1118, 52.6059) -> (49.1118, 54.0559)
  line L7 (55.6118, 52.6059) -> (49.1118, 52.6059)
  line L8 (55.6118, 60) -> (55.6118, 52.6059)
  line L9 (39.6118, 60) -> (55.6118, 60)
  line L10 (39.6118, 52.4859) -> (39.6118, 60)
  line L11 (32.9918, 52.4859) -> (39.6118, 52.4859)
  line L12 (32.9918, 53.9359) -> (32.9918, 52.4859)
  line L13 (28.7318, 53.9359) -> (32.9918, 53.9359)
  line L14 (28.7318, 45.6759) -> (28.7318, 53.9359)
  line L15 (32.9918, 45.6759) -> (28.7318, 45.6759)
  line L16 (32.9918, 47.1259) -> (32.9918, 45.6759)
  line L17 (39.6118, 47.1259) -> (32.9918, 47.1259)
  line L18 (39.6118, 10) -> (39.6118, 47.1259)
  line L19 (55.6118, 10) -> (39.6118, 10)
  line L20 (55.6118, 47.0059) -> (55.6118, 10)
  circle C1 centre (28.7318, 49.8059) radius 0.85
  circle C2 centre (44.6118, 49.8059) radius 0.85
  point P22 (28.7318, 49.8059)
  point P23 (44.6118, 49.8059)
  midpoint L14 P22
  midpoint L4 P23
  dimension "d247" diameter C1 = 1.7 (= "filament_hole_width")
  dimension "d250" diameter C2 = 1.7 (= "filament_hole_width")
extrude "Extrude12" cut sketch "Sketch9" profile of L4 L14 C1 C2 no distance stored
sketch "Sketch16" plane through (0, 19.6118, 0) normal (0, -1, 0) x axis (1, 0, 0)
  line L1 (0, 60) -> (40, 60)
  line L2 (40, 23.2332) -> (0, 23.2332)
  curve K1
  curve K2
  curve K3
  curve K4
  line L3 (40, 60) -> (40, 23.2332)
  line L4 (0, 23.2332) -> (0, 60)
  line L5 (14.0949, 43.2512) -> (13.8576, 43.2561)
  line L6 (14.0327, 40.2395) -> (14.0949, 43.2512)
  line L7 (13.6644, 40.2471) -> (14.0327, 40.2395)
  line L8 (13.7129, 42.5938) -> (13.6644, 40.2471)
  curve K5 (13.3578, 42.3474) -> (13.7129, 42.5938)
  curve K6 (12.9672, 42.1651) -> (13.3578, 42.3474)
  line L9 (12.9745, 42.5211) -> (12.9672, 42.1651)
  curve K7 (13.5219, 42.8618) -> (12.9745, 42.5211)
  curve K8 (13.8576, 43.2561) -> (13.5219, 42.8618)
  line L10 (17.2592, 40.1729) -> (17.7336, 41.8353)
  line L11 (16.8745, 40.1808) -> (17.2592, 40.1729)
  line L12 (16.2545, 42.3674) -> (16.8745, 40.1808)
  line L13 (16.635, 42.3595) -> (16.2545, 42.3674)
  line L14 (16.9549, 41.0982) -> (16.635, 42.3595)
  line L15 (17.0741, 40.629) -> (16.9549, 41.0982)
  curve K9 (17.1959, 41.0748) -> (17.0741, 40.629)
  line L16 (17.568, 42.3402) -> (17.1959, 41.0748)
  line L17 (17.9465, 42.3324) -> (17.568, 42.3402)
  line L18 (18.2457, 41.0654) -> (17.9465, 42.3324)
  line L19 (18.3456, 40.6478) -> (18.2457, 41.0654)
  line L20 (18.4791, 41.0646) -> (18.3456, 40.6478)
  line L21 (18.8774, 42.3132) -> (18.4791, 41.0646)
  line L22 (19.2354, 42.3058) -> (18.8774, 42.3132)
  line L23 (18.5113, 40.147) -> (19.2354, 42.3058)
  line L24 (18.1287, 40.1549) -> (18.5113, 40.147)
  line L25 (17.8098, 41.4633) -> (18.1287, 40.1549)
  line L26 (17.7336, 41.8353) -> (17.8098, 41.4633)
  curve K10 (20.366, 40.3605) -> (19.9904, 40.5094)
  curve K11 (20.8203, 40.5517) -> (20.366, 40.3605)
  line L27 (16.085, 41.0977) -> (16.0926, 41.468)
  line L28 (14.9536, 41.1211) -> (16.085, 41.0977)
  line L29 (14.9612, 41.4914) -> (14.9536, 41.1211)
  line L30 (16.0926, 41.468) -> (14.9612, 41.4914)
  line L31 (11.6001, 40.2898) -> (12.4674, 42.4456)
  line L32 (11.2563, 40.2969) -> (11.6001, 40.2898)
  line L33 (10.4747, 42.4867) -> (11.2563, 40.2969)
  line L34 (10.8634, 42.4787) -> (10.4747, 42.4867)
  line L35 (11.303, 41.1679) -> (10.8634, 42.4787)
  curve K12 (11.4331, 40.7271) -> (11.303, 41.1679)
  curve K13 (11.5787, 41.1376) -> (11.4331, 40.7271)
  line L36 (12.0889, 42.4534) -> (11.5787, 41.1376)
  line L37 (12.4674, 42.4456) -> (12.0889, 42.4534)
  curve K14 (20.494, 42.0956) -> (19.9234, 41.919)
  curve K15 (19.9904, 40.5094) -> (19.8008, 40.9391)
  curve K16 (21.0154, 41.0798) -> (20.8203, 40.5517)
  curve K17 (20.8477, 41.5806) -> (21.0154, 41.0798)
  curve K18 (20.389, 41.7723) -> (20.8477, 41.5806)
  curve K19 (20.0661, 41.6971) -> (20.389, 41.7723)
  curve K20 (19.8368, 41.493) -> (20.0661, 41.6971)
  curve K21 (21.4068, 41.1045) -> (21.1512, 41.8098)
  curve K22 (21.155, 40.4056) -> (21.4068, 41.1045)
  line L38 (19.8008, 40.9391) -> (19.4134, 40.9144)
  curve K23 (21.1512, 41.8098) -> (20.494, 42.0956)
  curve K24 (19.6955, 40.3006) -> (20.3598, 40.0577)
  curve K25 (19.4134, 40.9144) -> (19.6955, 40.3006)
  line L39 (19.4919, 41.5452) -> (19.8368, 41.493)
  line L40 (19.8143, 43.0798) -> (19.4919, 41.5452)
  line L41 (21.3058, 43.049) -> (19.8143, 43.0798)
  line L42 (21.2985, 42.6971) -> (21.3058, 43.049)
  line L43 (20.1016, 42.7218) -> (21.2985, 42.6971)
  line L44 (19.9234, 41.919) -> (20.1016, 42.7218)
  curve K26 (20.3598, 40.0577) -> (21.155, 40.4056)
  curve K27 (29.014, 42.8447) -> (28.5925, 42.9517)
  curve K28 (29.309, 42.5582) -> (29.014, 42.8447)
  curve K29 (27.709, 42.2924) -> (27.5829, 41.4395)
  curve K30 (28.0446, 42.787) -> (27.709, 42.2924)
  curve K31 (28.5925, 42.9517) -> (28.0446, 42.787)
  curve K32 (29.4859, 42.1084) -> (29.309, 42.5582)
  curve K33 (26.9786, 42.6064) -> (26.6837, 42.8929)
  curve K34 (27.1556, 42.1565) -> (26.9786, 42.6064)
  curve K35 (25.3787, 42.3406) -> (25.2525, 41.4876)
  curve K36 (25.7143, 42.8351) -> (25.3787, 42.3406)
  curve K37 (26.2622, 42.9998) -> (25.7143, 42.8351)
  curve K38 (26.6837, 42.8929) -> (26.2622, 42.9998)
  curve K39 (27.8544, 40.214) -> (28.5292, 39.8889)
  curve K40 (27.5829, 41.4395) -> (27.8544, 40.214)
  curve K41 (29.5388, 41.3991) -> (29.4859, 42.1084)
  curve K42 (29.4128, 40.5481) -> (29.5388, 41.3991)
  curve K43 (29.0771, 40.0536) -> (29.4128, 40.5481)
  curve K44 (28.5292, 39.8889) -> (29.0771, 40.0536)
  curve K45 (22.0295, 40.3343) -> (22.7044, 40.0092)
  curve K46 (21.7581, 41.5598) -> (22.0295, 40.3343)
  curve K47 (21.8842, 42.4128) -> (21.7581, 41.5598)
  curve K48 (22.2198, 42.9073) -> (21.8842, 42.4128)
  curve K49 (22.7677, 43.072) -> (22.2198, 42.9073)
  curve K50 (23.1892, 42.9651) -> (22.7677, 43.072)
  curve K51 (23.4841, 42.6785) -> (23.1892, 42.9651)
  curve K52 (23.6611, 42.2287) -> (23.4841, 42.6785)
  curve K53 (23.714, 41.5194) -> (23.6611, 42.2287)
  curve K54 (23.5879, 40.6685) -> (23.714, 41.5194)
  curve K55 (23.2523, 40.1739) -> (23.5879, 40.6685)
  curve K56 (22.7044, 40.0092) -> (23.2523, 40.1739)
  curve K57 (25.524, 40.2621) -> (26.1989, 39.937)
  curve K58 (25.2525, 41.4876) -> (25.524, 40.2621)
  curve K59 (27.2085, 41.4472) -> (27.1556, 42.1565)
  curve K60 (27.0824, 40.5963) -> (27.2085, 41.4472)
  curve K61 (26.7468, 40.1017) -> (27.0824, 40.5963)
  curve K62 (26.1989, 39.937) -> (26.7468, 40.1017)
  line L45 (24.6839, 40.0195) -> (24.6926, 40.4389)
  line L46 (24.2645, 40.0282) -> (24.6839, 40.0195)
  line L47 (24.2732, 40.4476) -> (24.2645, 40.0282)
  line L48 (24.6926, 40.4389) -> (24.2732, 40.4476)
  circle C1 centre (20, 49.8059) radius 1.06
  point P2 (40, 23.2332)
  point P4 (0, 60)
  coincident P2
  coincident P4
  dimension "d253" Text1-Height = 3
extrude "Extrude22" cut sketch "Sketch16" against normal blind 2
extrude "Extrude23" cut sketch "Sketch15" profile of L7 C1 against normal blind 2000
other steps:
create_component "CreateComponent1"
create_component "CreateComponent2"
create_component "CreateComponent3"
create_component "CreateComponent4"
named bodies: "Wall anchor part", "Base plate with slot"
